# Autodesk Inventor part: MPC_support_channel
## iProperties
Shininess: 64.0
Length Units: 11269
Angle Units: 11279
Time Units: 11290
Mass Units: 11283
Length Display Precision: 3
Angle Display Precision: 2
Compacted: True
Part Number: MPC_support_channel
Document SubType Name: Modeling
Created: 2004-08
Designer: John Blackburn
Manufacturer: Standard
Standards Organization: Custom
Material: Aluminum-6061
Density: 0.0
Volumn: 0.0
Area: 0.0
PropertySet Name: Model Information
Control State: 0
Master: False
Checked Out: False
Author: John Blackburn
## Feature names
1. Extrusion1
